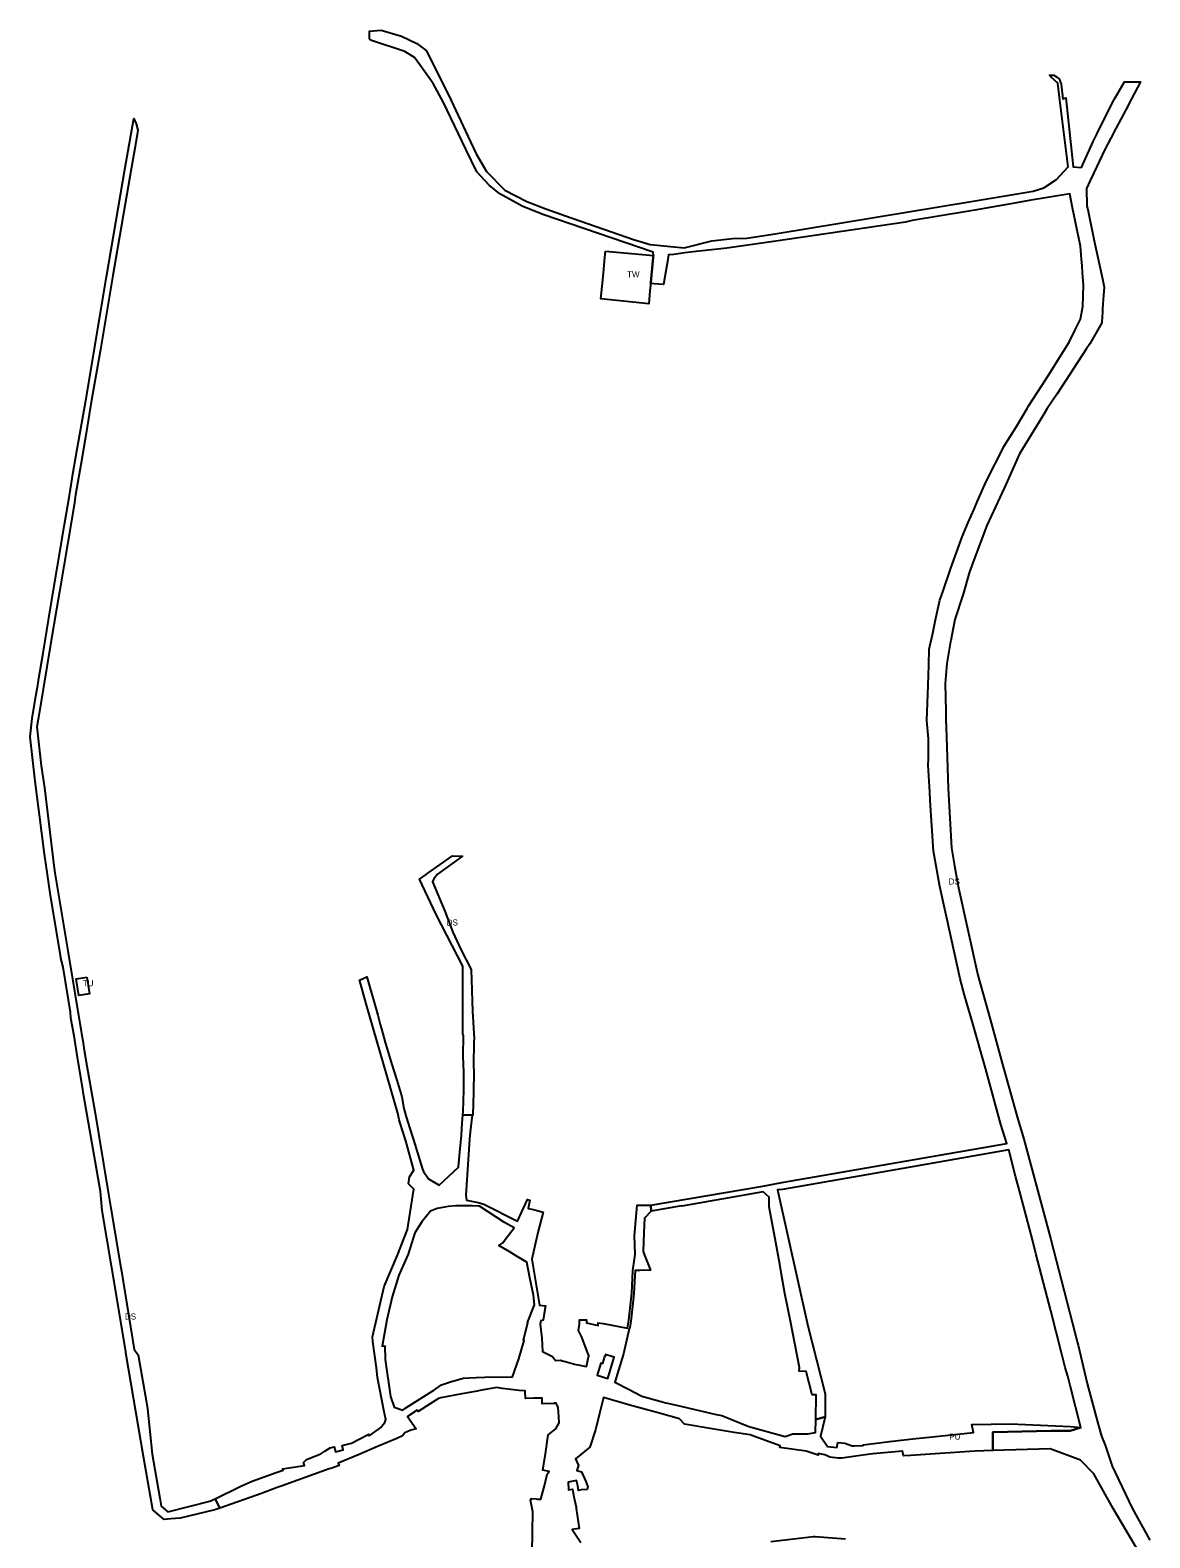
# Model space of a CAD drawing. Extents: x -540396 to -537847, y -1162344 to -1159959.
# Drawn here: x -540396 to -539467, y -1161210 to -1159959 of the extents above; entities that cross this region are included whole.
import ezdxf

# ---------------------------------------------------------------- set-up
doc = ezdxf.new("R2010")
doc.units = 0
for name, color, linetype in [('90320013', 7, 'Continuous'), ('90380013', 7, 'Continuous'), ('90390013', 7, 'Continuous'), ('90450013', 7, 'Continuous')]:
    doc.layers.add(name, color=color, linetype=linetype)

msp = doc.modelspace()

# ---------------------------------------------------------------- linework, layer by layer
at = {"layer": '90320013'}
msp.add_lwpolyline([(-539472.01, -1161228.75), (-539497.36, -1161186), (-539513.32, -1161157.12), (-539524.21, -1161145.9), (-539549.61, -1161136.48), (-539597.06, -1161137.85), (-539597.164, -1161122.777), (-539548.77, -1161121.52), (-539533.04, -1161121.61), (-539523.97, -1161118.87), (-539532.67, -1161085.08), (-539534.97, -1161076.16), (-539536.99, -1161068.99), (-539539.99, -1161056.65), (-539548.91, -1161021.98), (-539561.45, -1160974.35), (-539564.23, -1160963.09), (-539571.68, -1160934.67), (-539574.11, -1160925.41), (-539578.21, -1160910), (-539583.93, -1160888.29), (-539676.35, -1160904.54), (-539678.23, -1160904.87), (-539771.7, -1160921.26), (-539775.88, -1160921.568), (-539750.503, -1161034.411), (-539736.18, -1161090.79), (-539736.18, -1161109.88), (-539743.96, -1161112.02), (-539743.59, -1161091.78), (-539747.11, -1161091.71), (-539751.88, -1161072.28), (-539757.67, -1161072.11), (-539757.43, -1161068.92), (-539765.06, -1161030.47), (-539769.61, -1161007.52), (-539772.38, -1160991.76), (-539773.94, -1160983.2), (-539777.08, -1160965.17), (-539782.76, -1160935.46), (-539782.71, -1160927.53), (-539787.77, -1160923.22), (-539855.24, -1160935.05), (-539855.3, -1160934.7), (-539880.72, -1160939.17), (-539880.8, -1160934.07), (-539787.89, -1160918.34), (-539772.26, -1160915.27), (-539585.53, -1160883.06), (-539590.37, -1160867.23), (-539602.29, -1160823.36), (-539603.06, -1160820.51), (-539613.99, -1160782.56), (-539620.46, -1160759.86), (-539624.15, -1160746.4), (-539631.78, -1160712.13), (-539641.09, -1160669.51), (-539646.24, -1160640.35), (-539649.14, -1160598.17), (-539649.42, -1160590.92), (-539650.68, -1160568.9), (-539650.6, -1160563.3), (-539650.41, -1160548.28), (-539650.35, -1160547.02), (-539651.71, -1160531.92), (-539650.77, -1160502.39), (-539650.25, -1160485.84), (-539649.83, -1160472.69), (-539647.95, -1160463.89), (-539647.54, -1160461.93), (-539644.34, -1160446.97), (-539641.15, -1160432), (-539638.38, -1160424.12), (-539631.8, -1160405.4), (-539622.59, -1160379.21), (-539617.44, -1160367.38), (-539612.64, -1160356.38), (-539609.97, -1160350.24), (-539602.6, -1160333.33), (-539587.98, -1160304.74), (-539587.82, -1160304.43), (-539577.57, -1160287.59), (-539568.53, -1160272.74), (-539567.65, -1160271.23), (-539555.83, -1160252.97), (-539548.99, -1160242.09), (-539543.16, -1160232.76), (-539533.82, -1160217.78), (-539528.99, -1160208.07), (-539524.21, -1160198.49), (-539522.29, -1160187.99), (-539521.72, -1160170.16), (-539522.63, -1160160.16), (-539523.04, -1160154.15), (-539523.4, -1160148.87), (-539524.2, -1160138.12), (-539527.02, -1160124.61), (-539530.85, -1160106.21), (-539533.26, -1160094.63), (-539534.95, -1160094.86), (-539566.81, -1160100.08), (-539577.54, -1160102), (-539612.07, -1160108.19), (-539618.67, -1160109.28), (-539664, -1160116.8), (-539669.5, -1160118.03), (-539777.21, -1160133.77), (-539817.86, -1160139.54), (-539848.219, -1160143.04), (-539852.54, -1160143.49), (-539861.77, -1160144.89), (-539866.21, -1160145.17), (-539867.03, -1160150.82), (-539867.81, -1160155.49), (-539870.249, -1160169.921), (-539878.185, -1160169.34), (-539881.017, -1160169.127), (-539880.94, -1160168.3), (-539880.33, -1160162.02), (-539878.93, -1160147.41), (-539878.77, -1160145.8), (-539878.88, -1160142.86), (-539970.46, -1160111.61), (-539987.61, -1160104.72), (-540006.2, -1160094.54), (-540015.06, -1160087.48), (-540025.38, -1160076.27), (-540034.45, -1160057.61), (-540052.86, -1160018.84), (-540061.44, -1160002.94), (-540072.59, -1159987.34), (-540076.91, -1159981.29), (-540085.04, -1159976.32), (-540112.66, -1159967.27), (-540114.32, -1159965.74), (-540114.34, -1159959.41), (-540104.63, -1159958.67), (-540087.85, -1159963.71), (-540074.99, -1159969.67), (-540067.3, -1159975.45), (-540051.03, -1160008.01), (-540046.5, -1160017.09), (-540032.65, -1160046.74), (-540025.88, -1160061.24), (-540017.28, -1160076.06), (-540001.97, -1160091.42), (-539983.78, -1160100.94), (-539967.97, -1160107.08), (-539951.75, -1160112.76), (-539895.17, -1160132.58), (-539881.45, -1160136.75), (-539872.87, -1160137.5), (-539864.5, -1160138.25), (-539853.3, -1160139.26), (-539830.37, -1160133.62), (-539813.107, -1160131.779), (-539801.1, -1160131.48), (-539777.83, -1160127.75), (-539613.52, -1160100.78), (-539563.53, -1160092.42), (-539554.63, -1160089.47), (-539544.32, -1160082.78), (-539534.463, -1160072.073), (-539541.38, -1160016.88), (-539543.22, -1160002.75), (-539548.59, -1159997.61), (-539550.023, -1159996.124), (-539546.53, -1159995.95), (-539544.3, -1159997.55), (-539543.63, -1159998.03), (-539542.04, -1159999.17), (-539540.24, -1160003.61), (-539539, -1160015.66), (-539536.54, -1160014.93), (-539530.43, -1160072.14), (-539523.43, -1160072.73), (-539513.78, -1160051.22), (-539510.76, -1160045.13), (-539497.71, -1160018.84), (-539495.67, -1160014.74), (-539487.8, -1160001.56), (-539484.32, -1160001.54), (-539477.03, -1160001.5), (-539474.65, -1160001.49), (-539482.04, -1160015.57), (-539486.82, -1160024.7), (-539494.95, -1160040.2), (-539499.27, -1160048.44), (-539504.15, -1160057.74), (-539513.23, -1160077.01), (-539516.34, -1160083.61), (-539519.41, -1160090.12), (-539519.03, -1160104.35), (-539518.09, -1160108.82), (-539512.88, -1160133.53), (-539506.16, -1160165.16), (-539504.78, -1160171.93), (-539505.45, -1160182.31), (-539505.96, -1160190.04), (-539506.17, -1160193.22), (-539506.35, -1160196.13), (-539506.72, -1160201.77), (-539511.16, -1160209.5), (-539516.64, -1160219.04), (-539519.57, -1160223.53), (-539543.76, -1160260.52), (-539551.86, -1160272.91), (-539554.76, -1160277.35), (-539556.49, -1160280.21), (-539574.91, -1160310.55), (-539586.08, -1160335.4), (-539587.64, -1160338.97), (-539602.14, -1160370.05), (-539612.5, -1160397.88), (-539616.32, -1160408.3), (-539621.83, -1160426.91), (-539628.67, -1160447.82), (-539631.19, -1160460.88), (-539632.01, -1160465.71), (-539632.14, -1160466.29), (-539635.21, -1160484.43), (-539636.65, -1160500.97), (-539636.18, -1160524.12), (-539636.18, -1160530.77), (-539635.66, -1160545.36), (-539634.2, -1160588.33), (-539631.37, -1160637.5), (-539628.8, -1160652.38), (-539626.36, -1160666.27), (-539625.46, -1160670.68), (-539609.66, -1160743.12), (-539599.23, -1160779.87), (-539589.32, -1160816.2), (-539576.96, -1160860.94), (-539571.49, -1160879.49), (-539549.36, -1160961.61), (-539546.7, -1160971.15), (-539526.79, -1161048.34), (-539526.32, -1161050.29), (-539518.85, -1161082.11), (-539509.83, -1161115.28), (-539506.91, -1161125.99), (-539503.79, -1161133.46), (-539498.11, -1161150.86), (-539481.41, -1161185.77), (-539466.8, -1161212.37)], dxfattribs=at)
for points in [[(-540284.83, -1161195.14), (-540290.005, -1161190.693), (-540290.019, -1161190.681), (-540290.019, -1161190.681), (-540294.21, -1161187.08), (-540294.21, -1161187.08), (-540301.95, -1161142.81), (-540316.41, -1161056.82), (-540316.56, -1161055.73), (-540328.53, -1160984.68), (-540336.04, -1160938.56), (-540337.58, -1160922.86), (-540348.66, -1160859.5), (-540351.34, -1160843.57), (-540352.78, -1160834.49), (-540356.38, -1160813.29), (-540359.51, -1160793.49), (-540362.13, -1160778.82), (-540362.4, -1160773.82), (-540368.65, -1160736.51), (-540370.43, -1160729.11), (-540370.76, -1160726.58), (-540379.03, -1160677.01), (-540381.66, -1160659.6), (-540384.03, -1160642.85), (-540388.21, -1160610), (-540390.89, -1160588.89), (-540391.97, -1160579.55), (-540395.91, -1160545.34), (-540394.19, -1160530.11), (-540391.13, -1160511.56), (-540389.59, -1160502.47), (-540388.61, -1160496.72), (-540385.21, -1160475.93), (-540379.07, -1160438.35), (-540367.38, -1160369.03), (-540364.58, -1160352.98), (-540363.17, -1160344.9), (-540360.1, -1160325.54), (-540356.83, -1160306.42), (-540349.68, -1160266.25), (-540332.5, -1160163.53), (-540317.01, -1160072.74), (-540310.02, -1160032.13), (-540308.05, -1160036.54), (-540306.51, -1160041.57), (-540308.57, -1160053.59), (-540308.83, -1160055.13), (-540311.8, -1160072.45), (-540327.33, -1160162.37), (-540337.62, -1160223.7), (-540345.01, -1160265.76), (-540350.6, -1160299.99), (-540353.51, -1160317.83), (-540357.49, -1160339.82), (-540358.21, -1160344.57), (-540359.02, -1160350.72), (-540361.01, -1160362.65), (-540371.68, -1160425.08), (-540374.16, -1160439.26), (-540378.74, -1160467.09), (-540388.47, -1160525.94), (-540390.49, -1160537.06), (-540386.78, -1160569.5), (-540384.15, -1160587.81), (-540376.23, -1160652.23), (-540375.43, -1160658.17), (-540364.34, -1160724.7), (-540353.65, -1160790.09), (-540353.36, -1160791.66), (-540352.31, -1160797.72), (-540351.12, -1160805.53), (-540348.88, -1160818.39), (-540342.08, -1160857.75), (-540331.73, -1160920.05), (-540328.9, -1160936.63), (-540321.15, -1160982.89), (-540320.11, -1160989), (-540309.59, -1161053.9), (-540306.26, -1161058.41), (-540299.4, -1161097.97), (-540298.48, -1161103.29), (-540294.74, -1161140.88), (-540288.43, -1161177.55), (-540287.3, -1161184.12), (-540281.58, -1161188.7), (-540246.8, -1161180.03), (-540242.426, -1161177.868), (-540238.6, -1161185.61), (-540242.79, -1161187.03), (-540264.39, -1161192.38), (-540271.57, -1161194.17), (-540279.25, -1161194.73)], [(-540038.55, -1160721.9), (-540030.03, -1160738.43), (-540028.72, -1160773.19), (-540027.5, -1160796.19), (-540027.87, -1160797.94), (-540027.93, -1160818.42), (-540027.8, -1160823.41), (-540028.13, -1160840.36), (-540028.52, -1160859.45), (-540029.22, -1160859.38), (-540036.85, -1160859.24), (-540036.73, -1160856.44), (-540036.73, -1160856.44), (-540036.02, -1160838.65), (-540036.01, -1160823.95), (-540036.7, -1160810.45), (-540036.32, -1160793.36), (-540036.76, -1160792.2), (-540036.99, -1160780.5), (-540036.94, -1160768.85), (-540036.79, -1160756.7), (-540036.86, -1160747.95), (-540036.88, -1160735.75), (-540059.03, -1160692.85), (-540072.96, -1160663.43), (-540067.41, -1160659.58), (-540065.89, -1160658.49), (-540045.415, -1160644.122), (-540037.21, -1160644.48), (-540057.96, -1160659.35), (-540060.96, -1160663.22), (-540061.35, -1160663.86), (-540062.12, -1160665.66), (-540051.73, -1160690.03), (-540045.29, -1160707.57)]]:
    msp.add_lwpolyline(points, close=True, dxfattribs=at)
at = {"layer": '90380013'}
msp.add_lwpolyline([(-540349.01, -1160744.97), (-540346.71, -1160758.68), (-540355.54, -1160760.09), (-540357.81, -1160746.26)], close=True, dxfattribs=at)
at = {"layer": '90390013'}
msp.add_lwpolyline([(-539918.38, -1160142.14), (-539884.65, -1160145.26), (-539878.77, -1160145.8), (-539878.93, -1160147.41), (-539880.33, -1160162.02), (-539880.94, -1160168.3), (-539881.59, -1160175.1), (-539882.63, -1160185.93), (-539922.43, -1160181.71), (-539921.36, -1160171.22), (-539920.25, -1160160.44), (-539919.56, -1160153.7), (-539918.92, -1160147.4)], close=True, dxfattribs=at)
at = {"layer": '90450013'}
for points in [[(-539979.34, -1161222.69), (-539978.91, -1161188.87), (-539980.84, -1161179.23), (-539979.83, -1161177.73), (-539976.13, -1161178.07), (-539974.97, -1161178.13), (-539973.88, -1161178.23), (-539972.22, -1161178.38), (-539968.94, -1161166.18), (-539966.78, -1161157.47), (-539965.15, -1161155.17), (-539970.51, -1161154.32), (-539968.38, -1161140.74), (-539966.01, -1161124.8), (-539959.64, -1161119.79), (-539957.02, -1161114.93), (-539957.13, -1161110), (-539957.84, -1161102.21), (-539959.39, -1161098.47), (-539961, -1161098.56), (-539960.83, -1161098.96), (-539970.91, -1161099.06), (-539970.98, -1161094.37), (-539978.27, -1161094.5), (-539984.9, -1161094.59), (-539985.22, -1161089.01), (-539985.29, -1161088.42), (-539990.08, -1161087.97), (-540003.84, -1161086.39), (-540004.37, -1161086.26), (-540008.62, -1161085.62), (-540022.7, -1161088.11), (-540025.05, -1161088.55), (-540037.7, -1161090.93), (-540055.25, -1161094.24), (-540057, -1161094.57), (-540073.92, -1161105.55), (-540074.78, -1161104.28), (-540082.68, -1161109.63), (-540075.55, -1161119.86), (-540079.94, -1161121.06), (-540085.14, -1161123.15), (-540087.01, -1161125.82), (-540091.68, -1161127.8), (-540107.65, -1161134.58), (-540123.02, -1161141.1), (-540140.3, -1161148.43), (-540139.55, -1161150.22), (-540145.66, -1161152.44), (-540147.81, -1161153.21), (-540186.7, -1161167.22), (-540190.84, -1161168.71), (-540203.89, -1161173.54), (-540238.6, -1161185.61), (-540242.426, -1161177.868), (-540221.12, -1161167.34), (-540211.6, -1161163.37), (-540191.64, -1161156.26), (-540186.06, -1161154.17), (-540186.48, -1161153), (-540168.14, -1161150.44), (-540169.06, -1161147.69), (-540166.71, -1161145.31), (-540154.85, -1161140.64), (-540151.53, -1161138.45), (-540146.87, -1161135.53), (-540143.71, -1161134.83), (-540142.66, -1161139.07), (-540136.1, -1161137.44), (-540137.01, -1161133.62), (-540129.16, -1161131.68), (-540123.59, -1161128.82), (-540114.93, -1161124.38), (-540114.6, -1161125.62), (-540107.04, -1161120.37), (-540104.97, -1161118.64), (-540103.16, -1161116.69), (-540101.63, -1161114.48), (-540100.89, -1161112), (-540102.38, -1161104.26), (-540107.61, -1161077.15), (-540108.61, -1161069.28), (-540111.44, -1161047.5), (-540111.72, -1161043.54), (-540102.04, -1161001.75), (-540091.12, -1160975.75), (-540082.8, -1160954.31), (-540077.43, -1160920.94), (-540081.88, -1160916.49), (-540081.13, -1160910.54), (-540077.66, -1160905.09), (-540084.16, -1160880.75), (-540089.24, -1160865.24), (-540089.83, -1160863.21), (-540090.94, -1160857.78), (-540117.04, -1160766.9), (-540121.54, -1160750.93), (-540122.56, -1160747.33), (-540116.53, -1160744.57), (-540113.13, -1160756.33), (-540110.71, -1160764.79), (-540107.47, -1160776.56), (-540105.34, -1160784.11), (-540104.44, -1160787.85), (-540101.24, -1160799.21), (-540100.88, -1160800.67), (-540096.19, -1160816.54), (-540091.53, -1160830.3), (-540087.52, -1160844.38), (-540085.76, -1160853.86), (-540083.8, -1160860.89), (-540080.92, -1160870.46), (-540077.9, -1160879.94), (-540073.62, -1160893.64), (-540070.3, -1160904.43), (-540069.4, -1160906.11), (-540065.39, -1160912.27), (-540056.42, -1160917.7), (-540040.5, -1160902.74), (-540040.46, -1160902.24), (-540039.4, -1160890.18), (-540038.06, -1160876), (-540037.41, -1160866.12), (-540036.85, -1160859.24), (-540029.22, -1160859.38), (-540030.5, -1160871.03), (-540031.01, -1160876.31), (-540031.34, -1160879.5), (-540034.27, -1160925.89), (-540033.9, -1160929.99), (-540024.05, -1160932.08), (-540019.43, -1160933.44), (-539991.62, -1160947.42), (-539983.16, -1160929.41), (-539981.29, -1160930.09), (-539982.63, -1160937), (-539979.7, -1160937.58), (-539976.44, -1160938.46), (-539970.32, -1160939.99), (-539974.54, -1160957.01), (-539977.7, -1160970.37), (-539979.75, -1160979.04), (-539973.32, -1161017.1), (-539968.34, -1161017.83), (-539969.39, -1161024.09), (-539970.16, -1161029.53), (-539972.1, -1161030.21), (-539972.57, -1161033.09), (-539971.45, -1161044.55), (-539971.2, -1161044.53), (-539970.83, -1161055.77), (-539968.09, -1161057.12), (-539962.58, -1161059.85), (-539960.01, -1161063.01), (-539956.21, -1161062.93), (-539948.99, -1161064.82), (-539944.95, -1161065.88), (-539944.67, -1161065.94), (-539944.36, -1161066.06), (-539941.17, -1161066.83), (-539935.95, -1161067.75), (-539934.19, -1161068.1), (-539933.11, -1161062.98), (-539932.26, -1161058.92), (-539933.63, -1161055.68), (-539938.11, -1161043.76), (-539939.39, -1161041.14), (-539940.95, -1161038.36), (-539939.97, -1161032.92), (-539940.01, -1161029.41), (-539939.34, -1161029.41), (-539936.15, -1161029.37), (-539934.21, -1161029.35), (-539934.18, -1161031.97), (-539924.48, -1161034.12), (-539924.55, -1161031.74), (-539920.45, -1161032.5), (-539900.16, -1161036.39), (-539899.17, -1161029.67), (-539896.71, -1161007.27), (-539895.93, -1160988.44), (-539894.5, -1160979.14), (-539893.98, -1160974.97), (-539894.43, -1160959.58), (-539892.26, -1160934.14), (-539880.8, -1160934.07), (-539880.72, -1160939.17), (-539886.12, -1160945.11), (-539886.65, -1160956.92), (-539887.35, -1160972.75), (-539886.03, -1160975.62), (-539881.21, -1160988.21), (-539890.12, -1160988.38), (-539893.82, -1160988.42), (-539894.88, -1161007.32), (-539895.26, -1161010.62), (-539897.45, -1161030.4), (-539898.31, -1161035.71), (-539898.77, -1161036.8), (-539903.67, -1161057.74), (-539910.83, -1161081), (-539899.4, -1161086.98), (-539888.35, -1161092.76), (-539868.48, -1161098.37), (-539859.69, -1161100.32), (-539826.58, -1161108.02), (-539822, -1161108.93), (-539799.55, -1161117.89), (-539769.52, -1161126.27), (-539763.11, -1161124.13), (-539750.69, -1161123.99), (-539744.18, -1161122.9), (-539743.96, -1161112.02), (-539736.18, -1161109.88), (-539740.01, -1161126), (-539734.19, -1161134.48), (-539726.48, -1161135.43), (-539725.8, -1161131.12), (-539719.81, -1161131.84), (-539713.79, -1161133.93), (-539711.98, -1161133.88), (-539704.68, -1161133.8), (-539704.71, -1161133.18), (-539691.46, -1161131.59), (-539682.76, -1161130.41), (-539661.1, -1161127.89), (-539647.02, -1161126.43), (-539613.08, -1161122.91), (-539614.61, -1161116.17), (-539582.3, -1161115.66), (-539532.52, -1161117.9), (-539523.97, -1161118.87), (-539533.04, -1161121.61), (-539548.77, -1161121.52), (-539597.164, -1161122.777), (-539597.06, -1161137.85), (-539604.51, -1161138.05), (-539612.071, -1161138.538), (-539665.41, -1161141.98), (-539671.19, -1161142.35), (-539672.02, -1161138.53), (-539696.7, -1161140.71), (-539703.04, -1161141.59), (-539722.25, -1161144.33), (-539725.35, -1161144.3), (-539732.44, -1161143.47), (-539734.67, -1161142.39), (-539736.5, -1161141.5), (-539742.11, -1161140.48), (-539742.15, -1161141.62), (-539752.06, -1161138.55), (-539773.86, -1161135.32), (-539773.66, -1161133.96), (-539797.18, -1161125.28), (-539798.46, -1161124.81), (-539811.64, -1161122.79), (-539831.74, -1161119.68), (-539853.06, -1161115.99), (-539857.21, -1161111.67), (-539874.86, -1161106.68), (-539898.32, -1161100.11), (-539920.13, -1161094), (-539923.34, -1161107.21), (-539926.72, -1161120.83), (-539931.51, -1161135), (-539943.34, -1161144.85), (-539940.94, -1161150.22), (-539942.34, -1161154.33), (-539938.54, -1161155.59), (-539934.95, -1161163.62), (-539933.13, -1161167.9), (-539933.74, -1161170.15), (-539938.64, -1161170.54), (-539940.79, -1161171.01), (-539941.55, -1161167.18), (-539942.43, -1161162.77), (-539949.49, -1161164.19), (-539949.33, -1161170.49), (-539945.91, -1161169.87), (-539944.66, -1161176.2), (-539942.94, -1161185.02), (-539942.88, -1161186.15), (-539940.44, -1161202.49), (-539946.14, -1161203.53), (-539938.93, -1161214.23)], [(-539781.34, -1161213.37), (-539745.98, -1161209.27), (-539744.56, -1161209.39), (-539719.26, -1161211.25)]]:
    msp.add_lwpolyline(points, dxfattribs=at)
for points in [[(-540096.91, -1161093.07), (-540093.82, -1161101.79), (-540093.08, -1161102.05), (-540087.6, -1161103.98), (-540086.78, -1161104.3), (-540084.93, -1161103.12), (-540081.88, -1161101.17), (-540061.7, -1161088.24), (-540061.24, -1161087.99), (-540054.64, -1161083.44), (-540047.23, -1161080.73), (-540036.61, -1161077.88), (-540031.68, -1161077.6), (-540025.81, -1161077.21), (-540018.55, -1161077.08), (-539995.71, -1161076.69), (-539990.5, -1161061.76), (-539985.96, -1161046.44), (-539986.52, -1161046.28), (-539982.95, -1161031.7), (-539983.17, -1161031.64), (-539977.29, -1161017.02), (-539978.28, -1161008.97), (-539981.42, -1160994.45), (-539983.82, -1160981.44), (-539991.68, -1160976.82), (-539998.56, -1160972.77), (-540007.08, -1160967.8), (-540003.78, -1160965.33), (-540000.8, -1160961.69), (-539994.24, -1160953), (-540002.44, -1160948.52), (-540023.02, -1160935.01), (-540028.79, -1160934.79), (-540033.48, -1160934.62), (-540042.82, -1160934.8), (-540049.15, -1160935.21), (-540058.2, -1160936.98), (-540063.64, -1160939.16), (-540070.92, -1160948.01), (-540076.76, -1160957.06), (-540082.37, -1160974.82), (-540089.97, -1160992.24), (-540095.42, -1161010.17), (-540100.07, -1161029.49), (-540103.86, -1161051.31), (-540101.48, -1161051.1), (-540101.38, -1161062.18)], [(-539913.15, -1161059.74), (-539918.41, -1161058.16), (-539918.88, -1161059.69), (-539919.26, -1161059.57), (-539919.61, -1161060.75), (-539921.1, -1161065.7), (-539922.38, -1161065.32), (-539925.41, -1161075.37), (-539916.5, -1161078.05), (-539911.17, -1161060.33)]]:
    msp.add_lwpolyline(points, close=True, dxfattribs=at)

# ---------------------------------------------------------------- texts
at = {"layer": '90320013'}
for p in [(-539633.688, -1160667.965), (-540050.23, -1160702.005), (-540317.255, -1161029.109)]:
    msp.add_text('DS', height=5, rotation=360, dxfattribs=at).set_placement(p)
at = {"layer": '90380013'}
msp.add_text('TU', height=5, rotation=360, dxfattribs=at).set_placement((-540352.26, -1160752.506))
at = {"layer": '90390013'}
msp.add_text('TW', height=5, dxfattribs=at).set_placement((-539900.6, -1160163.905))
at = {"layer": '90450013'}
msp.add_text('PU', height=5, rotation=0, dxfattribs=at).set_placement((-539633.151, -1161128.83))

doc.saveas('drawing.dxf')
